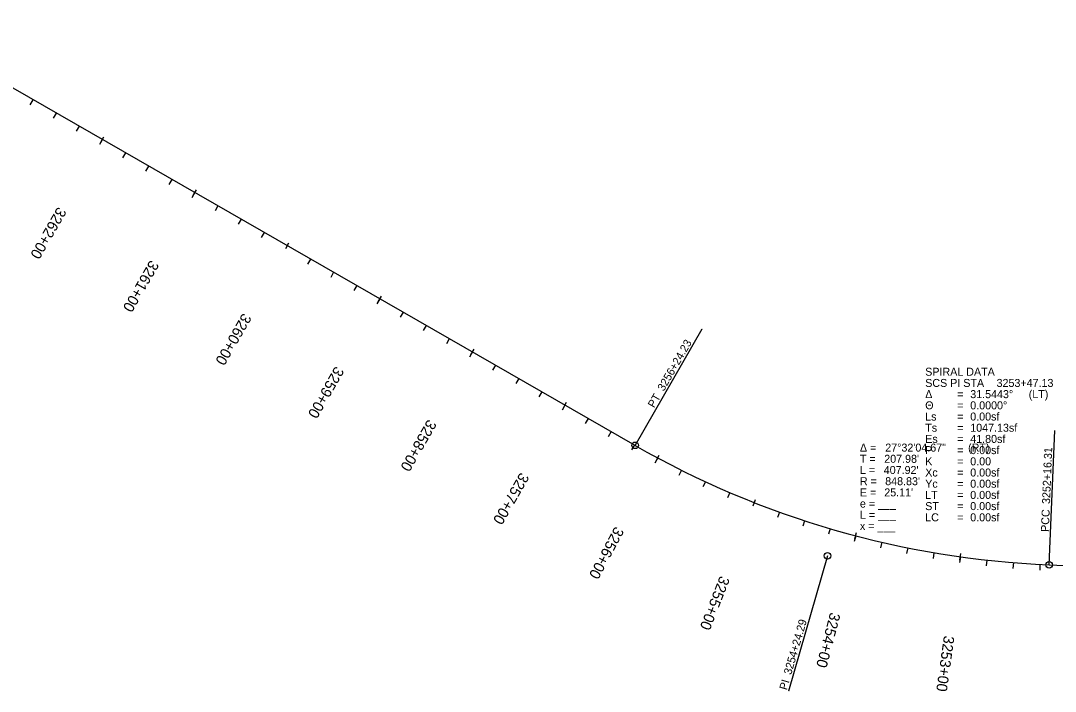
# Model space of a CAD drawing. Extents: x 15451313 to 15455081, y 8857737 to 8860760.
# Drawn here: x 15453192 to 15454162, y 8859058 to 8859687 of the extents above; entities that cross this region are included whole.
import ezdxf

# ---------------------------------------------------------------- set-up
doc = ezdxf.new("R2010")
doc.units = 0
for name, color, linetype in [('Annotation', 7, 'Continuous'), ('PC_REVISION_ANNOTATION', 7, 'Continuous'), ('SheetAddenda', 7, 'Continuous'), ('TextNonPlot', 7, 'Continuous')]:
    doc.layers.add(name, color=color, linetype=linetype)

msp = doc.modelspace()

# ---------------------------------------------------------------- linework, layer by layer
at = {"layer": 'Annotation'}
msp.add_line((15453768.03, 8859288.78), (15453074.6, 8859686.96), dxfattribs=at)
for centre, radius, start, end in [((15454190.72, 8860024.88), 848.83, 240.13449, 267.66912), ((15454688.71, 8872259.4), 13093.48, 267.66912, 271.678795)]:
    msp.add_arc(centre, radius, start, end, dxfattribs=at)
at = {"layer": 'PC_REVISION_ANNOTATION'}
for p, q in [((15453203.68, 8859612.84), (15453200.96, 8859608.11)), ((15453225.36, 8859600.39), (15453222.64, 8859595.66)), ((15453247.04, 8859587.94), (15453244.32, 8859583.21)), ((15453267.2, 8859572.84), (15453270.25, 8859578.15)), ((15453290.4, 8859563.04), (15453287.68, 8859558.31)), ((15453312.08, 8859550.59), (15453309.36, 8859545.86)), ((15453333.76, 8859538.15), (15453331.04, 8859533.41)), ((15453353.92, 8859523.04), (15453356.97, 8859528.35)), ((15453377.12, 8859513.25), (15453374.4, 8859508.51)), ((15453398.8, 8859500.8), (15453396.08, 8859496.06)), ((15453420.48, 8859488.35), (15453417.76, 8859483.61)), ((15453440.64, 8859473.25), (15453443.69, 8859478.55)), ((15453463.84, 8859463.45), (15453461.12, 8859458.72)), ((15453485.52, 8859451), (15453482.8, 8859446.27)), ((15453507.2, 8859438.55), (15453504.48, 8859433.82)), ((15453527.36, 8859423.45), (15453530.41, 8859428.76)), ((15453550.56, 8859413.65), (15453547.84, 8859408.92)), ((15453572.24, 8859401.21), (15453569.52, 8859396.47)), ((15453593.92, 8859388.76), (15453591.2, 8859384.02)), ((15453614.08, 8859373.65), (15453617.13, 8859378.96)), ((15453637.28, 8859363.86), (15453634.56, 8859359.12)), ((15453658.96, 8859351.41), (15453656.24, 8859346.67)), ((15453680.64, 8859338.96), (15453677.92, 8859334.22)), ((15453700.8, 8859323.86), (15453703.85, 8859329.16)), ((15453724, 8859314.06), (15453721.28, 8859309.33)), ((15453745.68, 8859301.61), (15453742.96, 8859296.88)), ((15453767.36, 8859289.16), (15453764.64, 8859284.43)), ((15453787.76, 8859274.32), (15453790.66, 8859279.71)), ((15453811.41, 8859265.52), (15453808.97, 8859260.63)), ((15453833.93, 8859254.68), (15453831.64, 8859249.72)), ((15453856.77, 8859244.5), (15453854.62, 8859239.48)), ((15453878.77, 8859232.16), (15453881.02, 8859237.85)), ((15453903.29, 8859226.2), (15453901.44, 8859221.06)), ((15453926.93, 8859218.08), (15453925.24, 8859212.89)), ((15453950.81, 8859210.66), (15453949.26, 8859205.42)), ((15453974.11, 8859200.99), (15453975.67, 8859206.91)), ((15453999.16, 8859197.95), (15453997.93, 8859192.63)), ((15454023.59, 8859192.67), (15454022.52, 8859187.31)), ((15454048.17, 8859188.11), (15454047.26, 8859182.72)), ((15454072.45, 8859181.24), (15454073.3, 8859187.3)), ((15454097.68, 8859181.17), (15454097.08, 8859175.74)), ((15454122.57, 8859178.79), (15454122.13, 8859173.35)), ((15454147.51, 8859177.15), (15454147.23, 8859171.7))]:
    msp.add_line(p, q, dxfattribs=at)
at = {"layer": 'SheetAddenda'}
for p, q in [((15453268.72, 8859575.49), (15453266, 8859570.76)), ((15453355.44, 8859525.7), (15453352.72, 8859520.96)), ((15453440.64, 8859473.25), (15453443.69, 8859478.55)), ((15453528.88, 8859426.1), (15453526.16, 8859421.37)), ((15453615.6, 8859376.31), (15453612.88, 8859371.57)), ((15453702.32, 8859326.51), (15453699.6, 8859321.78)), ((15453789.21, 8859277.02), (15453786.63, 8859272.2)), ((15453878.77, 8859232.16), (15453881.02, 8859237.85)), ((15453974.89, 8859203.95), (15453973.5, 8859198.67)), ((15454072.88, 8859184.27), (15454072.12, 8859178.86))]:
    msp.add_line(p, q, dxfattribs=at)
at = {"layer": 'TextNonPlot'}
for p, q in [((15453768.03, 8859288.78), (15453830.77, 8859398.05)), ((15453830.77, 8859398.05), (15453830.77, 8859398.05)), ((15454156.19, 8859176.75), (15454161.32, 8859302.65)), ((15454156.19, 8859176.75), (15454161.32, 8859302.65)), ((15454161.32, 8859302.65), (15454161.32, 8859302.65)), ((15454161.32, 8859302.65), (15454161.32, 8859302.65)), ((15453948.39, 8859185.21), (15453911.79, 8859058.39)), ((15453911.79, 8859058.39), (15453911.79, 8859058.39))]:
    msp.add_line(p, q, dxfattribs=at)
for centre in [(15453768.03, 8859288.78), (15453948.39, 8859185.21), (15454156.19, 8859176.75), (15454156.19, 8859176.75)]:
    msp.add_circle(centre, 3.12, dxfattribs=at)

# ---------------------------------------------------------------- texts
at = {"layer": 'PC_REVISION_ANNOTATION'}
for s, rotation, p in [('3262+00', 240.13449, (15453227.03, 8859512.95)), ('3261+00', 240.13449, (15453313.75, 8859463.15)), ('3260+00', 240.13449, (15453400.47, 8859413.36)), ('3259+00', 240.13449, (15453487.19, 8859363.56)), ('3258+00', 240.13449, (15453573.91, 8859313.76)), ('3257+00', 240.13449, (15453660.63, 8859263.97)), ('3256+00', 241.77004, (15453749.32, 8859213.31)), ('3255+00', 248.52001, (15453847.77, 8859167.05)), ('3254+00', 255.26998, (15453950.97, 8859132.69)), ('3253+00', 262.01995, (15454057.5, 8859110.69))]:
    msp.add_text(s, height=10.02, rotation=rotation, dxfattribs=at).set_placement(p)
at = {"layer": 'SheetAddenda'}
for s, rotation, p in [('3260+00', 240.13449, (15453400.47, 8859413.36)), ('3255+00', 248.52001, (15453847.77, 8859167.05))]:
    msp.add_text(s, height=10.02, rotation=rotation, dxfattribs=at).set_placement(p)
at = {"layer": 'TextNonPlot'}
for s, rotation, p in [('3256+24.23', 60.13449, (15453794.99, 8859339.03)), ('PT', 60.13449, (15453785.95, 8859323.3)), ('3252+16.31', 87.66912, (15454156.86, 8859233.67)), ('3252+16.31', 87.66912, (15454156.86, 8859233.67)), ('PCC', 87.66912, (15454155.8, 8859207.46)), ('PCC', 87.66912, (15454155.8, 8859207.46)), ('3254+24.29', 73.90181, (15453914.35, 8859073.21)), ('PI ', 73.90181, (15453910.2, 8859058.85))]:
    msp.add_text(s, height=7.5, rotation=rotation, dxfattribs=at).set_placement(p)
for s, p in [('SPIRAL DATA', (15454039.94, 8859354.04)), ('SCS PI STA ', (15454039.94, 8859343.54)), ('3253+47.13', (15454106.82, 8859343.54)), ('Δ', (15454039.94, 8859333.04)), ('= ', (15454069.94, 8859333.04)), ('31.5443°', (15454082.14, 8859333.04)), (' (LT)', (15454134.16, 8859333.04)), ('Θ ', (15454039.94, 8859322.54)), ('= ', (15454069.94, 8859322.54)), ('0.0000°', (15454082.14, 8859322.54)), ('Ls', (15454039.94, 8859312.04)), ('= ', (15454069.94, 8859312.04)), ('0.00sf', (15454082.14, 8859312.04)), ('Ts', (15454039.94, 8859301.54)), ('= ', (15454069.94, 8859301.54)), ('1047.13sf', (15454082.14, 8859301.54)), ('Es', (15454039.94, 8859291.04)), ('= ', (15454069.94, 8859291.04)), ('41.80sf', (15454082.14, 8859291.04)), ('Δ = ', (15453978.75, 8859282.91)), ('27°32\'04.67"', (15454002.49, 8859282.91)), ('P', (15454039.94, 8859280.54)), ('= ', (15454069.94, 8859280.54)), (' (RT)', (15454077.35, 8859282.91)), ('0.00sf', (15454082.14, 8859280.54)), ('T = ', (15453978.75, 8859272.41)), ("207.98'", (15454001.55, 8859272.41)), ('K', (15454039.94, 8859270.04)), ('= ', (15454069.94, 8859270.04)), ('0.00', (15454082.14, 8859270.04)), ('L = ', (15453978.75, 8859261.91)), ("407.92'", (15454001.09, 8859261.91)), ('Xc', (15454039.94, 8859259.54)), ('0.00sf', (15454082.14, 8859259.54)), ('R = ', (15453978.75, 8859251.41)), ("848.83'", (15454002.45, 8859251.41)), ('Yc', (15454039.94, 8859249.04)), ('= ', (15454069.94, 8859259.54)), ('0.00sf', (15454082.14, 8859249.04)), ('E = ', (15453978.75, 8859240.91)), ("25.11'", (15454001.56, 8859240.91)), ('= ', (15454069.94, 8859249.04)), ('0.00sf', (15454082.14, 8859238.54)), ('LT', (15454039.94, 8859238.54)), ('= ', (15454069.94, 8859238.54)), ('e = ___ ', (15453978.75, 8859230.41)), ('L = ___', (15453978.75, 8859219.91)), ('ST ', (15454039.94, 8859228.04)), ('= ', (15454069.94, 8859228.04)), ('0.00sf', (15454082.14, 8859228.04)), ('LC', (15454039.94, 8859217.54)), ('= ', (15454069.94, 8859217.54)), ('0.00sf', (15454082.14, 8859217.54)), ('x = ___', (15453978.75, 8859209.41))]:
    msp.add_text(s, height=7.5, dxfattribs=at).set_placement(p)

doc.saveas('drawing.dxf')
